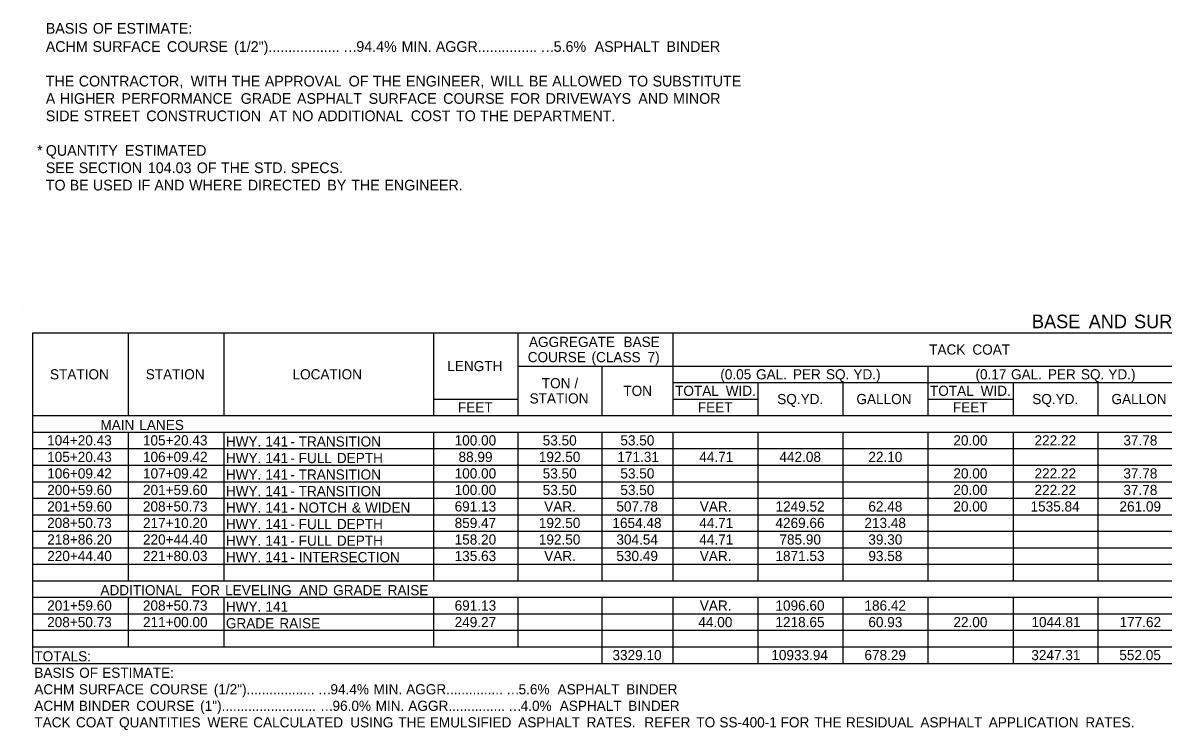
# Model space of a CAD drawing. Extents: x 1334738 to 1334853, y 402732 to 402753.
# Drawn here: x 1334821.77 to 1334837.83, y 402732.47 to 402742.43 of the extents above; entities that cross this region are included whole.
import ezdxf

# ---------------------------------------------------------------- set-up
doc = ezdxf.new("R2010")
doc.units = 0
doc.layers.add('Default', color=7, linetype='Continuous')

msp = doc.modelspace()

# ---------------------------------------------------------------- linework, layer by layer
at = {"layer": 'Default'}
for p, q in [((1334821.773, 402738.388), (1334821.773, 402738.388)), ((1334821.913, 402738.063), (1334853.053, 402738.063)), ((1334821.913, 402733.415), (1334821.913, 402738.063)), ((1334821.913, 402733.415), (1334821.913, 402738.063)), ((1334823.261, 402736.901), (1334823.261, 402738.063)), ((1334824.608, 402736.901), (1334824.608, 402738.063)), ((1334827.56, 402736.901), (1334827.56, 402738.063)), ((1334828.745, 402736.901), (1334828.745, 402738.063)), ((1334830.929, 402736.901), (1334830.929, 402738.063)), ((1334828.745, 402737.598), (1334853.053, 402737.598)), ((1334829.93, 402736.901), (1334829.93, 402737.598)), ((1334834.52, 402737.366), (1334834.52, 402737.598)), ((1334834.52, 402736.901), (1334834.52, 402737.598)), ((1334830.929, 402737.366), (1334838.11, 402737.366)), ((1334832.126, 402736.901), (1334832.126, 402737.366)), ((1334833.323, 402736.901), (1334833.323, 402737.366)), ((1334835.717, 402736.901), (1334835.717, 402737.366)), ((1334835.717, 402736.901), (1334835.717, 402737.366)), ((1334836.913, 402736.901), (1334836.913, 402737.366)), ((1334827.56, 402737.133), (1334828.745, 402737.133)), ((1334828.745, 402736.901), (1334828.745, 402737.133)), ((1334830.929, 402737.133), (1334832.126, 402737.133)), ((1334832.126, 402736.901), (1334832.126, 402737.133)), ((1334834.52, 402737.133), (1334835.717, 402737.133)), ((1334821.913, 402736.901), (1334853.053, 402736.901)), ((1334828.745, 402736.901), (1334832.126, 402736.901)), ((1334832.126, 402736.901), (1334835.717, 402736.901)), ((1334835.717, 402736.901), (1334836.913, 402736.901)), ((1334836.913, 402736.901), (1334840.306, 402736.901)), ((1334821.913, 402736.668), (1334853.053, 402736.668)), ((1334823.261, 402734.577), (1334823.261, 402736.668)), ((1334823.261, 402734.577), (1334823.261, 402736.668)), ((1334824.608, 402734.577), (1334824.608, 402736.668)), ((1334824.608, 402734.577), (1334824.608, 402736.668)), ((1334827.56, 402734.577), (1334827.56, 402736.668)), ((1334827.56, 402734.577), (1334827.56, 402736.668)), ((1334828.745, 402734.577), (1334828.745, 402736.668)), ((1334828.745, 402734.577), (1334828.745, 402736.668)), ((1334829.93, 402734.577), (1334829.93, 402736.668)), ((1334829.93, 402734.577), (1334829.93, 402736.668)), ((1334830.929, 402734.577), (1334830.929, 402736.668)), ((1334830.929, 402734.577), (1334830.929, 402736.668)), ((1334832.126, 402734.577), (1334832.126, 402736.668)), ((1334832.126, 402734.577), (1334832.126, 402736.668)), ((1334833.323, 402734.577), (1334833.323, 402736.668)), ((1334833.323, 402734.577), (1334833.323, 402736.668)), ((1334834.52, 402734.577), (1334834.52, 402736.668)), ((1334834.52, 402734.577), (1334834.52, 402736.668)), ((1334835.717, 402734.577), (1334835.717, 402736.668)), ((1334835.717, 402734.577), (1334835.717, 402736.668)), ((1334836.913, 402734.577), (1334836.913, 402736.668)), ((1334836.913, 402734.577), (1334836.913, 402736.668)), ((1334821.913, 402736.436), (1334853.053, 402736.436)), ((1334821.913, 402736.204), (1334853.053, 402736.204)), ((1334821.913, 402735.971), (1334853.053, 402735.971)), ((1334821.913, 402735.739), (1334853.053, 402735.739)), ((1334821.913, 402735.506), (1334853.053, 402735.506)), ((1334821.913, 402735.274), (1334853.053, 402735.274)), ((1334821.913, 402735.042), (1334853.053, 402735.042)), ((1334821.913, 402734.809), (1334853.053, 402734.809)), ((1334821.913, 402734.577), (1334832.126, 402734.577)), ((1334821.913, 402734.577), (1334853.053, 402734.577)), ((1334832.126, 402734.577), (1334834.52, 402734.577)), ((1334834.52, 402734.577), (1334835.717, 402734.577)), ((1334835.717, 402734.577), (1334839.307, 402734.577)), ((1334821.913, 402734.344), (1334853.053, 402734.344)), ((1334823.261, 402733.647), (1334823.261, 402734.344)), ((1334823.261, 402733.647), (1334823.261, 402734.344)), ((1334824.608, 402734.344), (1334827.56, 402734.344)), ((1334824.608, 402733.647), (1334824.608, 402734.344)), ((1334824.608, 402733.647), (1334824.608, 402734.344)), ((1334827.56, 402733.647), (1334827.56, 402734.344)), ((1334827.56, 402733.647), (1334827.56, 402734.344)), ((1334828.745, 402733.647), (1334828.745, 402734.344)), ((1334828.745, 402733.647), (1334828.745, 402734.344)), ((1334829.93, 402733.415), (1334829.93, 402734.344)), ((1334829.93, 402733.415), (1334829.93, 402734.344)), ((1334830.929, 402733.415), (1334830.929, 402734.344)), ((1334830.929, 402733.415), (1334830.929, 402734.344)), ((1334832.126, 402733.415), (1334832.126, 402734.344)), ((1334832.126, 402733.415), (1334832.126, 402734.344)), ((1334833.323, 402733.415), (1334833.323, 402734.344)), ((1334833.323, 402733.415), (1334833.323, 402734.344)), ((1334834.52, 402733.415), (1334834.52, 402734.344)), ((1334834.52, 402733.415), (1334834.52, 402734.344)), ((1334835.717, 402733.415), (1334835.717, 402734.344)), ((1334835.717, 402733.415), (1334835.717, 402734.344)), ((1334836.913, 402733.647), (1334836.913, 402734.344)), ((1334836.913, 402733.415), (1334836.913, 402734.344)), ((1334821.913, 402734.112), (1334853.053, 402734.112)), ((1334821.913, 402733.88), (1334853.053, 402733.88)), ((1334821.913, 402733.647), (1334853.053, 402733.647)), ((1334821.913, 402733.647), (1334853.053, 402733.647)), ((1334821.913, 402733.415), (1334853.053, 402733.415))]:
    msp.add_line(p, q, dxfattribs=at)

# ---------------------------------------------------------------- texts
for s, height, p in [('BASIS', 0.15, (1334822.097, 402742.274)), (' OF', 0.15, (1334822.703, 402742.274)), (' ESTIMATE:', 0.15, (1334823.043, 402742.274)), ('ACHM', 0.15, (1334822.097, 402742.018)), (' SURFACE', 0.15, (1334822.698, 402742.018)), (' COURSE', 0.15, (1334823.747, 402742.018)), (' (1/2")..................', 0.15, (1334824.691, 402742.018)), ('94.4%', 0.15, (1334826.468, 402742.018)), (' MIN.', 0.15, (1334827.049, 402742.018)), (' AGGR...............', 0.15, (1334827.531, 402742.018)), ('5.6%', 0.15, (1334829.246, 402742.018)), ('  ASPHALT', 0.15, (1334829.711, 402742.018)), (' BINDER', 0.15, (1334830.778, 402742.018)), ('…', 0.15, (1334826.283, 402742.018)), ('…', 0.15, (1334829.061, 402742.018)), ('THE', 0.15, (1334822.097, 402741.531)), (' CONTRACTOR,', 0.15, (1334822.505, 402741.531)), (' WITH', 0.15, (1334824.081, 402741.531)), (' THE', 0.15, (1334824.658, 402741.531)), (' APPROVAL', 0.15, (1334825.124, 402741.531)), (' OF', 0.15, (1334826.305, 402741.531)), (' THE', 0.15, (1334826.645, 402741.531)), (' ENGINEER,', 0.15, (1334827.111, 402741.531)), (' WILL', 0.15, (1334828.304, 402741.531)), (' BE', 0.15, (1334828.843, 402741.531)), (' ALLOWED', 0.15, (1334829.17, 402741.531)), (' TO', 0.15, (1334830.242, 402741.531)), (' SUBSTITUTE', 0.15, (1334830.582, 402741.531)), ('A', 0.15, (1334822.097, 402741.287)), (' HIGHER', 0.15, (1334822.237, 402741.287)), (' PERFORMANCE', 0.15, (1334823.107, 402741.287)), (' GRADE', 0.15, (1334824.785, 402741.287)), (' ASPHALT', 0.15, (1334825.577, 402741.287)), (' SURFACE', 0.15, (1334826.586, 402741.287)), (' COURSE', 0.15, (1334827.635, 402741.287)), (' FOR', 0.15, (1334828.579, 402741.287)), (' DRIVEWAYS', 0.15, (1334829.077, 402741.287)), (' AND', 0.15, (1334830.382, 402741.287)), (' MINOR', 0.15, (1334830.871, 402741.287)), ('SIDE', 0.15, (1334822.097, 402741.043)), (' STREET', 0.15, (1334822.575, 402741.043)), (' CONSTRUCTION', 0.15, (1334823.456, 402741.043)), (' AT', 0.15, (1334825.185, 402741.043)), (' NO', 0.15, (1334825.507, 402741.043)), (' ADDITIONAL', 0.15, (1334825.87, 402741.043)), (' COST', 0.15, (1334827.179, 402741.043)), (' TO', 0.15, (1334827.815, 402741.043)), (' THE', 0.15, (1334828.155, 402741.043)), (' DEPARTMENT.', 0.15, (1334828.621, 402741.043)), ('*', 0.15, (1334821.974, 402740.556)), ('QUANTITY', 0.15, (1334822.097, 402740.556)), (' ESTIMATED', 0.15, (1334823.155, 402740.556)), ('SEE', 0.15, (1334822.097, 402740.312)), (' SECTION', 0.15, (1334822.505, 402740.312)), (' 104.03', 0.15, (1334823.478, 402740.312)), (' OF', 0.15, (1334824.167, 402740.312)), (' THE', 0.15, (1334824.507, 402740.312)), (' STD.', 0.15, (1334824.973, 402740.312)), (' SPECS.', 0.15, (1334825.49, 402740.312)), ('TO', 0.15, (1334822.097, 402740.068)), (' BE', 0.15, (1334822.378, 402740.068)), (' USED', 0.15, (1334822.705, 402740.068)), (' IF', 0.15, (1334823.334, 402740.068)), (' AND', 0.15, (1334823.569, 402740.068)), (' WHERE', 0.15, (1334824.059, 402740.068)), (' DIRECTED', 0.15, (1334824.886, 402740.068)), (' BY', 0.15, (1334826.004, 402740.068)), (' THE', 0.15, (1334826.341, 402740.068)), (' ENGINEER.', 0.15, (1334826.807, 402740.068)), ('BASE', 0.1907, (1334835.979, 402738.13)), (' AND', 0.1907, (1334836.707, 402738.13)), (' SURFACING', 0.1907, (1334837.345, 402738.13)), ('AGGREGATE', 0.143, (1334828.898, 402737.866)), (' BASE', 0.143, (1334830.176, 402737.866)), ('COURSE', 0.143, (1334828.881, 402737.652)), (' (CLASS', 0.143, (1334829.726, 402737.652)), (' 7)', 0.143, (1334830.515, 402737.652)), ('TACK', 0.143, (1334834.532, 402737.759)), (' COAT', 0.143, (1334835.087, 402737.759)), ('LENGTH', 0.143, (1334827.749, 402737.526)), ('STATION', 0.143, (1334822.156, 402737.41)), ('STATION', 0.143, (1334823.504, 402737.41)), ('LOCATION', 0.143, (1334825.57, 402737.41)), (' /', 0.143, (1334829.485, 402737.285)), ('(0.05', 0.143, (1334831.592, 402737.41)), (' GAL.', 0.143, (1334832.042, 402737.41)), (' PER', 0.143, (1334832.561, 402737.41)), (' SQ.', 0.143, (1334833.026, 402737.41)), (' YD.)', 0.143, (1334833.412, 402737.41)), ('(0.17', 0.143, (1334835.184, 402737.41)), (' GAL.', 0.143, (1334835.631, 402737.41)), (' PER', 0.143, (1334836.15, 402737.41)), (' SQ.', 0.143, (1334836.615, 402737.41)), (' YD.)', 0.143, (1334837.001, 402737.41)), ('TON', 0.143, (1334829.079, 402737.285)), ('TON', 0.143, (1334830.227, 402737.178)), ('TOTAL', 0.143, (1334830.955, 402737.178)), (' WID.', 0.143, (1334831.615, 402737.178)), ('TOTAL', 0.143, (1334834.543, 402737.178)), (' WID.', 0.143, (1334835.203, 402737.178)), ('STATION', 0.143, (1334828.907, 402737.071)), ('SQ.YD.', 0.143, (1334832.393, 402737.062)), ('GALLON', 0.143, (1334833.508, 402737.062)), ('SQ.YD.', 0.143, (1334835.983, 402737.062)), ('GALLON', 0.143, (1334837.098, 402737.062)), ('FEET', 0.143, (1334827.899, 402736.945)), ('FEET', 0.143, (1334831.275, 402736.945)), ('FEET', 0.143, (1334834.865, 402736.945)), ('MAIN', 0.143, (1334822.866, 402736.697)), (' LANES', 0.143, (1334823.36, 402736.697)), ('104+20.43', 0.143, (1334822.116, 402736.481)), ('105+20.43', 0.143, (1334823.464, 402736.481)), ('HWY.', 0.143, (1334824.632, 402736.465)), (' 141', 0.143, (1334825.136, 402736.465)), (' -', 0.143, (1334825.488, 402736.465)), (' TRANSITION', 0.14301, (1334825.604, 402736.465)), ('100.00', 0.143, (1334827.852, 402736.481)), ('53.50', 0.143, (1334829.092, 402736.481)), ('53.50', 0.143, (1334830.185, 402736.481)), ('20.00', 0.143, (1334834.873, 402736.481)), ('222.22', 0.143, (1334836.015, 402736.481)), ('37.78', 0.143, (1334837.266, 402736.481)), ('105+20.43', 0.143, (1334822.116, 402736.248)), ('106+09.42', 0.143, (1334823.465, 402736.248)), ('HWY.', 0.143, (1334824.632, 402736.232)), (' 141', 0.143, (1334825.136, 402736.232)), (' FULL', 0.143, (1334825.604, 402736.232)), (' DEPTH', 0.143, (1334826.141, 402736.232)), ('88.99', 0.143, (1334827.907, 402736.248)), ('192.50', 0.143, (1334829.037, 402736.248)), ('171.31', 0.143, (1334830.143, 402736.248)), ('44.71', 0.143, (1334831.296, 402736.248)), ('442.08', 0.143, (1334832.424, 402736.248)), ('22.10', 0.143, (1334833.676, 402736.248)), ('106+09.42', 0.143, (1334822.117, 402736.016)), ('107+09.42', 0.143, (1334823.465, 402736.016)), (' -', 0.143, (1334825.488, 402736.232)), ('100.00', 0.143, (1334827.852, 402736.016)), ('53.50', 0.143, (1334829.092, 402736.016)), ('53.50', 0.143, (1334830.185, 402736.016)), ('20.00', 0.143, (1334834.873, 402736.016)), ('222.22', 0.143, (1334836.015, 402736.016)), ('37.78', 0.143, (1334837.266, 402736.016)), ('HWY.', 0.143, (1334824.632, 402736)), (' 141', 0.143, (1334825.136, 402736)), (' -', 0.143, (1334825.488, 402736)), (' TRANSITION', 0.14301, (1334825.604, 402736)), ('200+59.60', 0.143, (1334822.117, 402735.783)), ('201+59.60', 0.143, (1334823.465, 402735.783)), ('HWY.', 0.143, (1334824.632, 402735.767)), (' 141', 0.143, (1334825.136, 402735.767)), (' -', 0.143, (1334825.488, 402735.767)), (' TRANSITION', 0.14301, (1334825.604, 402735.767)), ('100.00', 0.143, (1334827.852, 402735.783)), ('53.50', 0.143, (1334829.092, 402735.783)), ('53.50', 0.143, (1334830.185, 402735.783)), ('20.00', 0.143, (1334834.873, 402735.783)), ('222.22', 0.143, (1334836.015, 402735.783)), ('37.78', 0.143, (1334837.266, 402735.783)), ('201+59.60', 0.143, (1334822.117, 402735.551)), ('208+50.73', 0.143, (1334823.464, 402735.551)), ('HWY.', 0.143, (1334824.632, 402735.535)), (' 141', 0.143, (1334825.136, 402735.535)), (' NOTCH', 0.143, (1334825.604, 402735.535)), (' &', 0.143, (1334826.353, 402735.535)), (' WIDEN', 0.143, (1334826.538, 402735.535)), ('691.13', 0.143, (1334827.852, 402735.551)), ('VAR.', 0.143, (1334829.113, 402735.551)), ('507.78', 0.143, (1334830.129, 402735.551)), ('VAR.', 0.143, (1334831.303, 402735.551)), ('1249.52', 0.143, (1334832.369, 402735.551)), ('62.48', 0.143, (1334833.676, 402735.551)), ('20.00', 0.143, (1334834.873, 402735.551)), ('1535.84', 0.143, (1334835.959, 402735.551)), ('261.09', 0.143, (1334837.211, 402735.551)), (' -', 0.143, (1334825.488, 402735.535)), ('208+50.73', 0.143, (1334822.116, 402735.319)), ('217+10.20', 0.143, (1334823.465, 402735.319)), ('HWY.', 0.143, (1334824.632, 402735.303)), (' 141', 0.143, (1334825.136, 402735.303)), (' -', 0.143, (1334825.488, 402735.303)), (' FULL', 0.143, (1334825.604, 402735.303)), (' DEPTH', 0.143, (1334826.141, 402735.303)), ('859.47', 0.143, (1334827.852, 402735.319)), ('192.50', 0.143, (1334829.037, 402735.319)), ('1654.48', 0.143, (1334830.073, 402735.319)), ('44.71', 0.143, (1334831.296, 402735.319)), ('4269.66', 0.143, (1334832.368, 402735.319)), ('213.48', 0.143, (1334833.62, 402735.319)), ('218+86.20', 0.143, (1334822.117, 402735.086)), ('220+44.40', 0.143, (1334823.465, 402735.086)), ('HWY.', 0.143, (1334824.632, 402735.07)), (' 141', 0.143, (1334825.136, 402735.07)), (' FULL', 0.143, (1334825.604, 402735.07)), (' DEPTH', 0.143, (1334826.141, 402735.07)), ('158.20', 0.143, (1334827.852, 402735.086)), ('192.50', 0.143, (1334829.037, 402735.086)), ('304.54', 0.143, (1334830.129, 402735.086)), ('44.71', 0.143, (1334831.296, 402735.086)), ('785.90', 0.143, (1334832.424, 402735.086)), ('39.30', 0.143, (1334833.676, 402735.086)), (' -', 0.143, (1334825.488, 402735.07)), ('220+44.40', 0.143, (1334822.117, 402734.854)), ('221+80.03', 0.143, (1334823.464, 402734.854)), ('HWY.', 0.143, (1334824.632, 402734.838)), (' 141', 0.143, (1334825.136, 402734.838)), (' -', 0.143, (1334825.488, 402734.838)), (' INTERSECTION', 0.14301, (1334825.604, 402734.838)), ('135.63', 0.143, (1334827.852, 402734.854)), ('VAR.', 0.143, (1334829.113, 402734.854)), ('530.49', 0.143, (1334830.129, 402734.854)), ('VAR.', 0.143, (1334831.303, 402734.854)), ('1871.53', 0.143, (1334832.368, 402734.854)), ('93.58', 0.143, (1334833.676, 402734.854)), ('ADDITIONAL', 0.143, (1334822.866, 402734.373)), (' FOR', 0.143, (1334824.092, 402734.373)), (' LEVELING', 0.143, (1334824.568, 402734.373)), (' AND', 0.143, (1334825.611, 402734.373)), (' GRADE', 0.143, (1334826.089, 402734.373)), (' RAISE', 0.143, (1334826.856, 402734.373)), ('201+59.60', 0.143, (1334822.117, 402734.157)), ('208+50.73', 0.143, (1334823.464, 402734.157)), ('HWY.', 0.143, (1334824.632, 402734.141)), (' 141', 0.143, (1334825.136, 402734.141)), ('691.13', 0.143, (1334827.852, 402734.157)), ('VAR.', 0.143, (1334831.303, 402734.157)), ('1096.60', 0.143, (1334832.368, 402734.157)), ('186.42', 0.143, (1334833.621, 402734.157)), ('208+50.73', 0.143, (1334822.116, 402733.924)), ('211+00.00', 0.143, (1334823.465, 402733.924)), ('249.27', 0.143, (1334827.852, 402733.924)), ('44.00', 0.143, (1334831.283, 402733.924)), ('1218.65', 0.143, (1334832.368, 402733.924)), ('60.93', 0.143, (1334833.676, 402733.924)), ('22.00', 0.143, (1334834.873, 402733.924)), ('1044.81', 0.143, (1334835.972, 402733.924)), ('177.62', 0.143, (1334837.212, 402733.924)), ('GRADE', 0.143, (1334824.632, 402733.908)), (' RAISE', 0.143, (1334825.332, 402733.908)), ('TOTALS:', 0.143, (1334821.936, 402733.443)), ('3329.10', 0.143, (1334830.074, 402733.46)), ('10933.94', 0.143, (1334832.31, 402733.46)), ('678.29', 0.143, (1334833.621, 402733.46)), ('3247.31', 0.143, (1334835.97, 402733.46)), ('552.05', 0.143, (1334837.209, 402733.46)), ('BASIS', 0.143, (1334821.936, 402733.211)), (' OF', 0.143, (1334822.514, 402733.211)), (' ESTIMATE:', 0.143, (1334822.838, 402733.211)), ('ACHM', 0.143, (1334821.936, 402732.979)), (' SURFACE', 0.143, (1334822.509, 402732.979)), (' COURSE', 0.143, (1334823.509, 402732.979)), (' (1/2")..................', 0.14301, (1334824.409, 402732.979)), ('94.4%', 0.143, (1334826.104, 402732.979)), (' MIN.', 0.143, (1334826.657, 402732.979)), (' AGGR...............', 0.14301, (1334827.117, 402732.979)), ('5.6%', 0.143, (1334828.752, 402732.979)), ('  ASPHALT', 0.143, (1334829.195, 402732.979)), (' BINDER', 0.143, (1334830.213, 402732.979)), ('…', 0.143, (1334825.927, 402732.979)), ('…', 0.143, (1334828.576, 402732.979)), ('ACHM', 0.143, (1334821.936, 402732.746)), (' BINDER', 0.143, (1334822.509, 402732.746)), (' COURSE', 0.143, (1334823.317, 402732.746)), (' (1").........................', 0.14301, (1334824.217, 402732.746)), ('96.0%', 0.143, (1334826.133, 402732.746)), (' MIN.', 0.143, (1334826.687, 402732.746)), (' AGGR...............', 0.14301, (1334827.147, 402732.746)), ('4.0%', 0.143, (1334828.782, 402732.746)), ('  ASPHALT', 0.143, (1334829.225, 402732.746)), (' BINDER', 0.143, (1334830.243, 402732.746)), ('TACK', 0.143, (1334821.936, 402732.514)), (' COAT', 0.143, (1334822.469, 402732.514)), (' QUANTITIES', 0.14301, (1334823.075, 402732.514)), (' WERE', 0.143, (1334824.319, 402732.514)), (' CALCULATED', 0.14301, (1334824.964, 402732.514)), ('…', 0.143, (1334825.957, 402732.746)), (' USING', 0.143, (1334826.33, 402732.514)), (' THE', 0.143, (1334827.006, 402732.514)), (' EMULSIFIED', 0.14301, (1334827.45, 402732.514)), ('…', 0.143, (1334828.606, 402732.746)), (' ASPHALT', 0.143, (1334828.694, 402732.514)), (' RATES.', 0.143, (1334829.656, 402732.514)), ('  REFER', 0.143, (1334830.416, 402732.514)), (' TO', 0.143, (1334831.202, 402732.514)), (' SS-400-1', 0.143, (1334831.526, 402732.514)), (' FOR', 0.143, (1334832.388, 402732.514)), (' THE', 0.143, (1334832.863, 402732.514)), (' RESIDUAL', 0.143, (1334833.307, 402732.514)), (' ASPHALT', 0.143, (1334834.355, 402732.514)), (' APPLICATION', 0.14301, (1334835.317, 402732.514)), (' RATES.', 0.143, (1334836.678, 402732.514))]:
    msp.add_text(s, height=height, dxfattribs=at).set_placement(p)

doc.saveas('drawing.dxf')
